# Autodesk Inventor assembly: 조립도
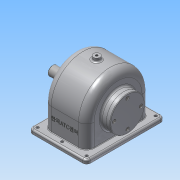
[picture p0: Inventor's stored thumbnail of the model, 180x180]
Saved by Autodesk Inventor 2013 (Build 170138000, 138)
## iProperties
Created: 2015-09
Part Number: 조립도
Document SubType Name: Assembly
Designer: semtle
Author: semtle
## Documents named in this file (14)
- C:\Users\semtle\Desktop\450907V1001\조립도.iam
- C:\Users\semtle\Desktop\450907V1001\본체.ipt
- C:\Users\semtle\Desktop\450907V1001\V-벨트풀리.ipt
- C:\Users\semtle\Desktop\450907V1001\뒤커버.ipt
- C:\Users\semtle\Desktop\450907V1001\멈춤나사 - M4x10.ipt
- C:\Users\semtle\Desktop\450907V1001\베어링 6203.ipt
- C:\Users\semtle\Desktop\450907V1001\볼트 M3 x 8.ipt
- C:\Users\semtle\Desktop\450907V1001\볼트 M3 x 10.ipt
- C:\Users\semtle\Desktop\450907V1001\스퍼기어.ipt
- C:\Users\semtle\Desktop\450907V1001\앞커버.ipt
- C:\Users\semtle\Desktop\450907V1001\오일 실 17 32 8.ipt
- C:\Users\semtle\Desktop\450907V1001\축.ipt
- C:\Users\semtle\Desktop\450907V1001\키 - 5 x 5 x 18.ipt
- C:\Users\semtle\Desktop\450907V1001\키 - 6 x 6 x 22.ipt
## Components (9 placed, 3 different names)
1. V-벨트풀리:1
2. ISO 4762 M3 x 8:1
3. ISO 4762 M3 x 10:1
4. ISO 4762 M3 x 8:2
5. ISO 4762 M3 x 8:3
6. ISO 4762 M3 x 8:4
7. ISO 4762 M3 x 10:2
8. ISO 4762 M3 x 10:3
9. ISO 4762 M3 x 10:4
